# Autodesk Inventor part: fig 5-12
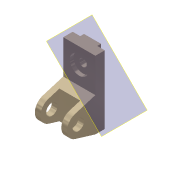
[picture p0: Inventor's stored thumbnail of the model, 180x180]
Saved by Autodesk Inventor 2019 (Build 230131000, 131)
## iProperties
Shininess: 65.0
Angle Display Precision: 2
Document Length Units: 11269
Document Angle Units: 11279
Document Time Units: 11290
Document Mass Units: 11283
Document Length Units Precision: 3
Document Angle Units Precision: 2
Compacted: False
Created: 2001-11
Part Number: fig 5-12
Document SubType Name: Modeling
Designer: Renu Muthoo
Density: 1 g/cm^3
Material: Generic
Appearance: Metal-Titanium (Polished)
Density: 0.0
Volumn: 0.0
Area: 0.0
PropertySet Name: Model Information
Control State: 0
Master: False
Checked Out: False
Author: Renu Muthoo
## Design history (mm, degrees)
node "Sketch1"
sketch "Sketch2"
  geometry: L1 (33.257, 104.664)-(33.257, -75.336); L2 (33.257, -75.336)-(8.257, -75.336); L3 (8.257, -75.336)-(-45.451, -59.045); L4 (-45.451, -1.628)-(8.257, 14.664); L5 (8.257, 14.664)-(8.257, 104.664); L6 (8.257, 104.664)-(33.257, 104.664); C1 r 15 at (-36.743, -30.336); A1 r 30 centre (-36.743, -30.336) between (-45.451, -1.628) and (-45.451, -59.045)
  constraints: 12 end point, 2 centre point, 2 equal length, 2 parallel, 2 point on circle, 2 tangent, 1 coincident, 1 perpendicular, 1 vertical
  dimensions: "d0" = 180 distance of L1.start L1.end; "d1" = 30 radius of A1; "d2" = 25 distance of L5.end L1.start; "d3" = 45 distance from line of L2 A1.centre; "d4" = 70 distance from line of L1 A1.centre; "d5" = 30 diameter of C1
extrude "Extrusion1" new body sketch "Sketch2" distance "d6" = 85; taper "d7" = 0 deg
workplane "Work Plane1"
sketch "Sketch3"
  geometry: L1 (15, 62.364)-(70, 62.364); L2 (70, 62.364)-(70, -52.386); L3 (70, -52.386)-(15, -52.386); L4 (15, -52.386)-(15, 62.364); L5 (0, -45)-(0, -28.708) reference
  constraints: 8 end point, 2 parallel, 1 horizontal, 1 perpendicular
  dimensions: "d8" = 55 distance of L1.start L1.end; "d9" = 15 distance between parallel lines of L5 L4
extrude "Extrusion2" cut sketch "Sketch3" distance "d10" = 50; taper "d11" = 0 deg
sketch "Sketch4"
  geometry: L1 (0, 25)-(85, 25) reference; L2 (0, 0)-(0, 25) reference; L3 (20, 25)-(65, 25); L4 (65, 25)-(65, 35); L5 (65, 35)-(20, 35); L6 (20, 35)-(20, 25)
  constraints: 8 end point, 2 parallel, 1 horizontal, 1 perpendicular, 1 point on line
  dimensions: "d12" = 45 distance of L4.end L5.end; "d13" = 10 distance of L3.end L4.end; "d14" = 20 distance between parallel lines of L2 L6
extrude "Extrusion3" join sketch "Sketch4" stored distance "d15" = 50; taper "d16" = 0 deg
sketch "Sketch5"
  geometry: L1 (85, 0)-(85, 90) reference; L2 (0, 90)-(85, 90) reference; 1 further point
  dimensions: "d17" = 42 distance from line of L2 point (42.5, 48); "d18" = 42.5 distance from line of L1 point (42.5, 48)
hole "Hole1" sketch "Sketch5" at (42.5, 48) diameter "d19" = 20; stored, may be unused: countersink angle "d23" = 82 deg, drill point angle "d25" = 118 deg; dims "d20" = 6, "d21" = 50, "d22" = 10, "d24" = 8
workplane "Work Plane8"
body "Solid1"
other parameters: "d28" = 135 deg
